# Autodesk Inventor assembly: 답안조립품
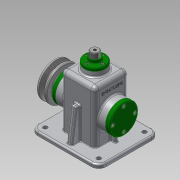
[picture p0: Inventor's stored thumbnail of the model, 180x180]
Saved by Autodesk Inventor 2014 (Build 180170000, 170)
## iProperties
Created: 2016-08
Part Number: 답안조립품
Document SubType Name: Assembly
Designer: user
Author: user
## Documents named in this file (19)
- C:\Users\user\Desktop\460820V1005\답안조립품.iam
- C:\Users\user\Desktop\460820V1005\본체.ipt
- C:\Users\user\Desktop\460820V1005\베어링 15 x 35 x 11.ipt
- C:\Users\user\Desktop\460820V1005\상부부시.ipt
- C:\Users\user\Desktop\460820V1005\앞커버.ipt
- C:\Users\user\Desktop\460820V1005\오일실 15 25 7.ipt
- C:\Users\user\Desktop\460820V1005\키 5 x 5 x 14.ipt
- C:\Users\user\Desktop\460820V1005\편심축.ipt
- C:\Users\user\Desktop\460820V1005\뒤커버.ipt
- C:\Users\user\Desktop\460820V1005\멈춤링 15 x 1.ipt
- C:\Users\user\Desktop\460820V1005\고정핀.ipt
- C:\Users\user\Desktop\460820V1005\링크.ipt
- C:\Users\user\Desktop\460820V1005\멈춤링 6 x 5.ipt
- C:\Users\user\Desktop\460820V1005\슬라이드바.ipt
- C:\Users\user\Desktop\460820V1005\V-벨트풀리.ipt
- C:\Users\user\Desktop\460820V1005\볼트 M4 x 10.ipt
- C:\Users\user\Desktop\460820V1005\볼트 M3 x 8.ipt
- C:\Users\user\Desktop\460820V1005\볼트 M6 x 12.ipt
- C:\Users\user\Desktop\460820V1005\와셔.ipt
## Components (15 placed, 5 different names)
1. 고정핀:1
2. V-벨트풀리:1 — 각도:1
3. ISO 4018 M6 x 12:1 — 강체:5
4. ISO 4762 M4 x 10:2 — 강체:1
5. ISO 4762 M4 x 10:3
6. ISO 4762 M4 x 10:4
7. ISO 4762 M4 x 10:5
8. ISO 4762 M4 x 10:1 — 강체:2
9. ISO 4762 M4 x 10:6
10. ISO 4762 M4 x 10:7
11. ISO 4762 M4 x 10:8
12. ISO 4762 M3 x 8:1 — 강체:3
13. ISO 4762 M3 x 8:2
14. ISO 4762 M3 x 8:3
15. ISO 4762 M3 x 8:4
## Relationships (5: WeldJoint 4, Angle 1)
- 각도:1 [Angle]: V-벨트풀리:1
- 강체:1 [WeldJoint]: ISO 4762 M4 x 10:2
- 강체:2 [WeldJoint]: ISO 4762 M4 x 10:1
- 강체:3 [WeldJoint]: ISO 4762 M3 x 8:1
- 강체:5 [WeldJoint]: ISO 4018 M6 x 12:1
